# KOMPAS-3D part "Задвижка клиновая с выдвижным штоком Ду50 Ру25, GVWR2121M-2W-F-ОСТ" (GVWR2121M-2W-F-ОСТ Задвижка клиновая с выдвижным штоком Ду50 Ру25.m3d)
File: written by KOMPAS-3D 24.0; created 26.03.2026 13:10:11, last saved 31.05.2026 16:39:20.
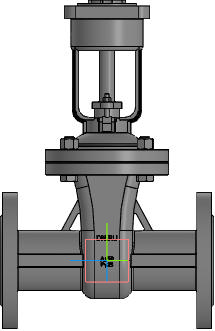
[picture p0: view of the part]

Document properties: Автор: R2D2; Полное имя файла: E:\Работа\Зайцев\GVWR2121M-2W-F-ОСТ Задвижка клиновая 30с964нж DN.ru Ду50-300 Ру25\исходные материалы\DN50\DN50\GVWR2121M-2W-F-ОСТ Задвижка клиновая с выдвижным штоком Ду50 Ру25.m3d

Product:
- Part/product: Задвижка клиновая с выдвижным штоком Ду50 Ру25  | designation GVWR2121M-2W-F-ОСТ
    Масса: 17
    Раздел спецификации: Прочие изделия
    Примечание: D040-09833

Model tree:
1. Операция без истории:1

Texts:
  GVWR2121M-2W-F-ОСТ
